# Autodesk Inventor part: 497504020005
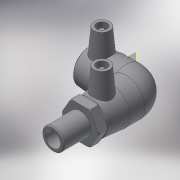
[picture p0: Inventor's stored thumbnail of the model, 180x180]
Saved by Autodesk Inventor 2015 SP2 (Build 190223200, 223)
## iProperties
Created: 2017-06
Part Number: 497504020005
Material: Generic
Description: PE Male Transition Elbow 90° 20x 1_2
Document SubType Name: Modeling
Designer: KIM
Mass: 88.5991 g
Surface Area: 264.343 cm^2
Volume: 88.5991 cm^3
Density: 1 g/cm^3
Appearance: Default
Author: KIM
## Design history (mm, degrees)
derived "497504.ipt"
feature "Solid1::497504.ipt"
feature "Solid2::497504.ipt"
tag "TaggingFeature1"
workplane "Work Plane2"
body "Solid1"
body "Solid2"
other parameters: "d2" = 36, "d4" = 20.66667, "d5" = 32.4, "d8" = 168 deg, "d10" = 14, "d11" = 4.66667, "d29" = 38, "d30" = 15, "d31" = 32.24, "d34" = 5 deg, "d41" = 4, "d42" = 14, "d43" = 0, "d48" = 44, "d50" = 2, "d51" = 14, "d52" = 35, "d54" = 90 deg, "d86" = 3, "d87" = 0, "d93" = 0.1, "d94" = 8.75, "d95" = 20.955, "d96" = 14.6685, "d97" = 14, "d98" = 35, "d99" = 36, "d100" = 31.5, "d102" = 1, "d106" = 0, "d108" = 31.5, "d114" = 35, "d115" = 0, "d116" = -35, "L_" = 97, "L_1" = 35, "D_" = 14, "A_" = 38, "d_2" = 12, "L_2" = 35, "D_1" = 36, "R_" = 20.955
